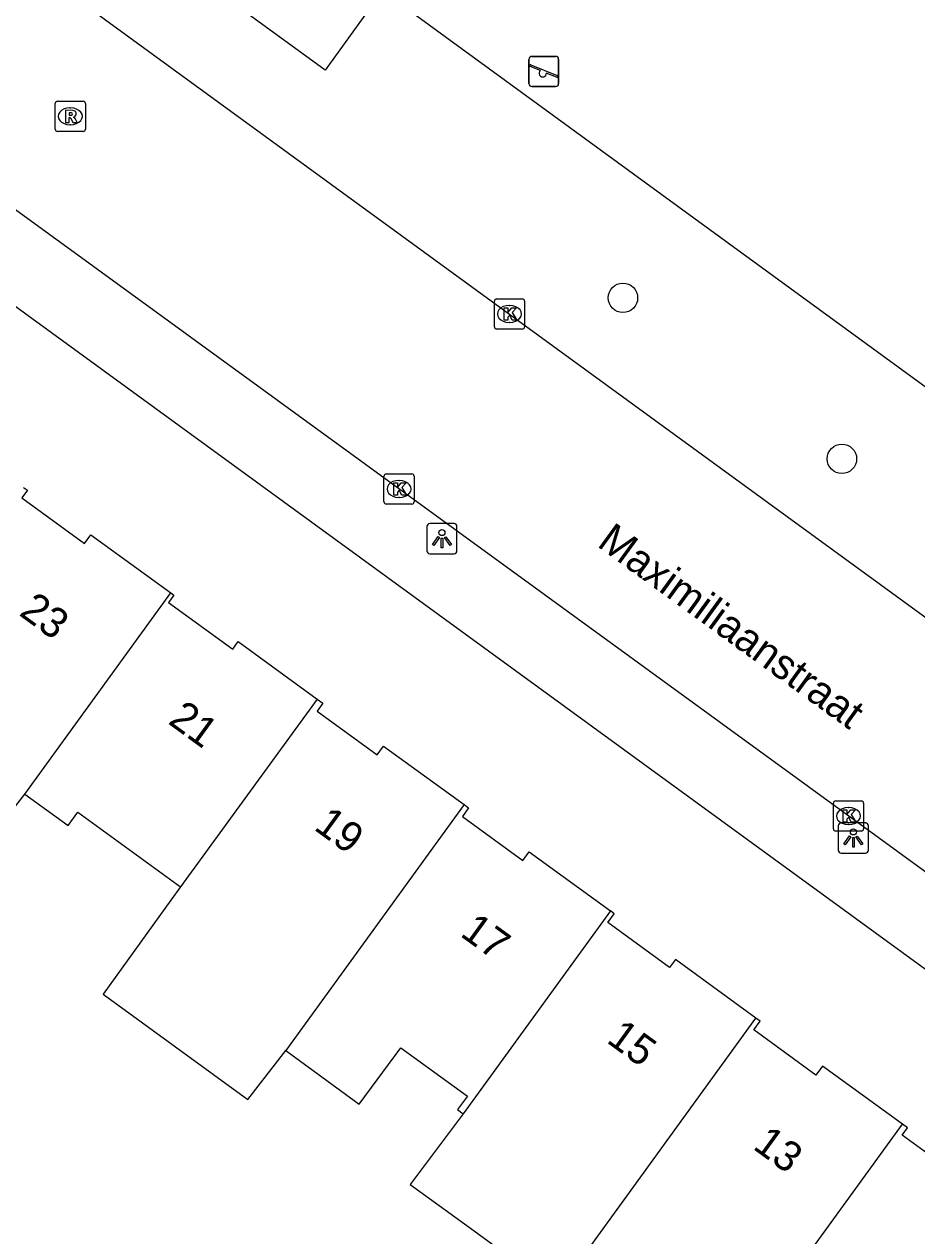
# Model space of a CAD drawing. Extents: x 159675 to 160530, y 382179 to 382901.
# Drawn here: x 160046.7 to 160076.32, y 382398.02 to 382438.2 of the extents above; entities that cross this region are included whole.
import ezdxf

# ---------------------------------------------------------------- set-up
doc = ezdxf.new("R2010")
doc.units = 0
for name, color, linetype in [('IMGEO_Boom', 7, 'Continuous'), ('IMGEO_Kolk', 7, 'Continuous'), ('IMGEO_Lichtpunt', 7, 'Continuous'), ('IMGEO_Openbare_ruimte_label', 7, 'Continuous'), ('IMGEO_Pand', 7, 'Continuous'), ('IMGEO_Pand_nummerreeks', 7, 'Continuous'), ('IMGEO_Rijbaan_lokaal_open', 7, 'Continuous'), ('IMGEO_Rioolput', 7, 'Continuous'), ('IMGEO_Speelvoorziening', 7, 'Continuous'), ('IMGEO_Voetpad_open', 7, 'Continuous')]:
    doc.layers.add(name, color=color, linetype=linetype)

msp = doc.modelspace()

# ---------------------------------------------------------------- linework, layer by layer
at = {"layer": 'IMGEO_Boom'}
for centre in [(160066.569, 382429.126), (160073.836, 382423.786)]:
    msp.add_circle(centre, 0.489, dxfattribs=at)
at = {"layer": 'IMGEO_Kolk'}
for p, q in [((160062.303, 382428.165), (160062.303, 382429.017)), ((160062.378, 382429.091), (160063.23, 382429.091)), ((160063.304, 382429.017), (160063.304, 382428.165)), ((160062.791, 382428.871), (160062.816, 382428.871)), ((160062.814, 382428.311), (160062.789, 382428.311)), ((160063.23, 382428.091), (160062.378, 382428.091)), ((160058.64, 382422.361), (160058.64, 382423.213)), ((160058.715, 382423.287), (160059.567, 382423.287)), ((160059.128, 382423.067), (160059.153, 382423.067)), ((160059.641, 382423.213), (160059.641, 382422.361)), ((160059.151, 382422.507), (160059.126, 382422.507)), ((160059.567, 382422.287), (160058.715, 382422.287)), ((160073.554, 382411.516), (160073.554, 382412.368)), ((160073.629, 382412.442), (160074.481, 382412.442)), ((160074.042, 382412.222), (160074.067, 382412.222)), ((160074.555, 382412.368), (160074.555, 382411.516)), ((160074.065, 382411.662), (160074.04, 382411.662)), ((160074.481, 382411.442), (160073.629, 382411.442))]:
    msp.add_line(p, q, dxfattribs=at)
for points in [[(160062.303, 382428.165), (160062.303, 382429.017)], [(160062.378, 382429.091), (160063.23, 382429.091)], [(160063.304, 382429.017), (160063.304, 382428.165)], [(160062.624, 382428.791), (160062.747, 382428.791), (160062.747, 382428.64), (160062.877, 382428.791), (160063.041, 382428.791), (160062.895, 382428.64), (160063.048, 382428.391), (160062.896, 382428.391), (160062.811, 382428.555), (160062.747, 382428.488), (160062.747, 382428.391), (160062.624, 382428.391), (160062.624, 382428.791)], [(160063.23, 382428.091), (160062.378, 382428.091)], [(160058.64, 382422.361), (160058.64, 382423.213)], [(160058.715, 382423.287), (160059.567, 382423.287)], [(160058.961, 382422.987), (160059.084, 382422.987), (160059.084, 382422.836), (160059.214, 382422.987), (160059.378, 382422.987), (160059.232, 382422.836), (160059.385, 382422.587), (160059.233, 382422.587), (160059.148, 382422.751), (160059.084, 382422.684), (160059.084, 382422.587), (160058.961, 382422.587), (160058.961, 382422.987)], [(160059.641, 382423.213), (160059.641, 382422.361)], [(160059.567, 382422.287), (160058.715, 382422.287)], [(160073.554, 382411.516), (160073.554, 382412.368)], [(160073.629, 382412.442), (160074.481, 382412.442)], [(160073.875, 382412.142), (160073.998, 382412.142), (160073.998, 382411.991), (160074.128, 382412.142), (160074.292, 382412.142), (160074.146, 382411.991), (160074.299, 382411.742), (160074.147, 382411.742), (160074.062, 382411.906), (160073.998, 382411.839), (160073.998, 382411.742), (160073.875, 382411.742), (160073.875, 382412.142)], [(160074.555, 382412.368), (160074.555, 382411.516)], [(160074.481, 382411.442), (160073.629, 382411.442)]]:
    msp.add_lwpolyline(points, dxfattribs=at)
for centre, start, end in [((160062.38, 382429.015), 91.552, 178.448), ((160062.38, 382429.015), 91.552, 178.448), ((160063.228, 382429.015), 1.552, 88.448), ((160063.228, 382429.015), 1.552, 88.448), ((160062.38, 382428.167), 181.552, 268.448), ((160062.38, 382428.167), 181.552, 268.448), ((160063.228, 382428.167), 271.552, 358.448), ((160063.228, 382428.167), 271.552, 358.448), ((160058.717, 382423.211), 91.552, 178.448), ((160058.717, 382423.211), 91.552, 178.448), ((160059.565, 382423.211), 1.552, 88.448), ((160059.565, 382423.211), 1.552, 88.448), ((160058.717, 382422.363), 181.552, 268.448), ((160058.717, 382422.363), 181.552, 268.448), ((160059.565, 382422.363), 271.552, 358.448), ((160059.565, 382422.363), 271.552, 358.448), ((160073.631, 382412.366), 91.552, 178.448), ((160073.631, 382412.366), 91.552, 178.448), ((160074.479, 382412.366), 1.552, 88.448), ((160074.479, 382412.366), 1.552, 88.448), ((160073.631, 382411.518), 181.552, 268.448), ((160073.631, 382411.518), 181.552, 268.448), ((160074.479, 382411.518), 271.552, 358.448), ((160074.479, 382411.518), 271.552, 358.448)]:
    msp.add_arc(centre, 0.0765, start, end, dxfattribs=at)
for centre, major_axis, ratio, start_param, end_param in [((160062.79, 382428.591), (-0.387, 0.002), 0.722429, 4.712389, 7.853982), ((160062.815, 382428.591), (-0.39, 0.002), 0.717154, 1.570796, 4.712389), ((160059.127, 382422.787), (-0.387, 0.002), 0.722429, 4.712389, 7.853982), ((160059.152, 382422.787), (-0.39, 0.002), 0.717154, 1.570796, 4.712389), ((160074.041, 382411.942), (-0.387, 0.002), 0.722429, 4.712389, 7.853982), ((160074.066, 382411.942), (-0.39, 0.002), 0.717154, 1.570796, 4.712389)]:
    msp.add_ellipse(centre, major_axis=major_axis, ratio=ratio, start_param=start_param, end_param=end_param, dxfattribs=at)
at = {"layer": 'IMGEO_Lichtpunt'}
for p, q in [((160060.065, 382421.543), (160060.065, 382420.736)), ((160060.065, 382421.543), (160060.065, 382420.736)), ((160060.967, 382421.638), (160060.159, 382421.638)), ((160060.967, 382421.638), (160060.159, 382421.638)), ((160061.061, 382420.736), (160061.061, 382421.543)), ((160061.061, 382420.736), (160061.061, 382421.543)), ((160060.159, 382420.642), (160060.967, 382420.642)), ((160060.159, 382420.642), (160060.967, 382420.642)), ((160074.619, 382411.71), (160073.811, 382411.71)), ((160074.619, 382411.71), (160073.811, 382411.71)), ((160073.717, 382411.615), (160073.717, 382410.808)), ((160073.717, 382411.615), (160073.717, 382410.808)), ((160074.713, 382410.808), (160074.713, 382411.615)), ((160074.713, 382410.808), (160074.713, 382411.615)), ((160073.811, 382410.714), (160074.619, 382410.714)), ((160073.811, 382410.714), (160074.619, 382410.714))]:
    msp.add_line(p, q, dxfattribs=at)
for points in [[(160060.439, 382421.207), (160060.478, 382421.179), (160060.29, 382420.917), (160060.252, 382420.944), (160060.439, 382421.207)], [(160060.541, 382421.159), (160060.588, 382421.159), (160060.588, 382420.837), (160060.541, 382420.837), (160060.541, 382421.159)], [(160060.651, 382421.179), (160060.689, 382421.206), (160060.876, 382420.944), (160060.837, 382420.916), (160060.651, 382421.179)], [(160074.091, 382411.279), (160074.13, 382411.251), (160073.942, 382410.989), (160073.904, 382411.016), (160074.091, 382411.279)], [(160074.303, 382411.251), (160074.341, 382411.278), (160074.528, 382411.016), (160074.489, 382410.988), (160074.303, 382411.251)], [(160074.193, 382411.231), (160074.24, 382411.231), (160074.24, 382410.909), (160074.193, 382410.909), (160074.193, 382411.231)]]:
    msp.add_lwpolyline(points, dxfattribs=at)
for centre in [(160060.564, 382421.341), (160074.216, 382411.413)]:
    msp.add_circle(centre, 0.0994, dxfattribs=at)
for centre, start, end in [((160060.159, 382421.543), 90, 180), ((160060.159, 382421.543), 90, 180), ((160060.967, 382421.543), 0, 90), ((160060.967, 382421.543), 0, 90), ((160060.159, 382420.736), 180, 270), ((160060.159, 382420.736), 180, 270), ((160060.967, 382420.736), 270, 0), ((160060.967, 382420.736), 270, 360), ((160073.811, 382411.615), 90, 180), ((160073.811, 382411.615), 90, 180), ((160074.619, 382411.615), 0, 90), ((160074.619, 382411.615), 0, 90), ((160073.811, 382410.808), 180, 270), ((160073.811, 382410.808), 180, 270), ((160074.619, 382410.808), 270, 0), ((160074.619, 382410.808), 270, 360)]:
    msp.add_arc(centre, 0.0946, start, end, dxfattribs=at)
at = {"layer": 'IMGEO_Pand'}
for points in [[(160046.682, 382422.833), (160046.805, 382422.744), (160046.62, 382422.49), (160048.7, 382420.976), (160048.913, 382421.27), (160051.563, 382419.341)], [(160046.719, 382412.671), (160051.563, 382419.341)], [(160051.563, 382419.341), (160051.661, 382419.269), (160051.485, 382419.028), (160053.62, 382417.473), (160053.804, 382417.726), (160056.422, 382415.82)], [(160042.201, 382416.661), (160040.904, 382414.902), (160045.725, 382411.376), (160045.904, 382411.621), (160046.719, 382412.671)], [(160056.422, 382415.82), (160051.892, 382409.591)], [(160056.422, 382415.82), (160056.613, 382415.681), (160056.422, 382415.419), (160058.412, 382413.969), (160058.626, 382414.263), (160061.297, 382412.318)], [(160046.719, 382412.671), (160048.156, 382411.625), (160048.483, 382412.073), (160051.892, 382409.591)], [(160061.297, 382412.318), (160055.378, 382404.167)], [(160061.297, 382412.318), (160061.448, 382412.208), (160061.245, 382411.93), (160063.252, 382410.469), (160063.461, 382410.756), (160066.154, 382408.795)], [(160051.892, 382409.591), (160051.57, 382409.148), (160049.32, 382406.038), (160054.119, 382402.544), (160055.378, 382404.167)], [(160066.154, 382408.795), (160061.268, 382402.066)], [(160070.984, 382405.234), (160068.311, 382407.18), (160068.119, 382406.918), (160066.069, 382408.41), (160066.282, 382408.702), (160066.154, 382408.795)], [(160065.185, 382397.247), (160070.984, 382405.234)], [(160075.846, 382401.717), (160073.194, 382403.648), (160072.976, 382403.347), (160070.91, 382404.851), (160071.118, 382405.136), (160070.984, 382405.234)], [(160055.378, 382404.167), (160057.817, 382402.39), (160059.203, 382404.258), (160061.406, 382402.654), (160061.078, 382402.204), (160061.268, 382402.066)], [(160061.268, 382402.066), (160059.51, 382399.725), (160061.629, 382398.181), (160064.228, 382396.288), (160064.398, 382396.164), (160065.185, 382397.247)], [(160070.065, 382393.754), (160075.846, 382401.717)], [(160080.833, 382398.104), (160078.087, 382400.103), (160077.906, 382399.854), (160075.84, 382401.359), (160076.013, 382401.596), (160075.846, 382401.717)]]:
    msp.add_lwpolyline(points, dxfattribs=at)
at = {"layer": 'IMGEO_Rijbaan_lokaal_open'}
for points in [[(160018.366, 382460.946), (160123.455, 382384.426)], [(160099.29, 382393.592), (160034.415, 382440.769)]]:
    msp.add_lwpolyline(points, dxfattribs=at)
at = {"layer": 'IMGEO_Rioolput'}
for p, q in [((160047.729, 382434.721), (160047.729, 382435.573)), ((160047.804, 382435.647), (160048.656, 382435.647)), ((160048.217, 382435.427), (160048.242, 382435.427)), ((160048.73, 382435.573), (160048.73, 382434.721)), ((160048.656, 382434.647), (160047.804, 382434.647)), ((160048.24, 382434.867), (160048.215, 382434.867))]:
    msp.add_line(p, q, dxfattribs=at)
for points in [[(160047.729, 382434.721), (160047.729, 382435.573)], [(160047.804, 382435.647), (160048.656, 382435.647)], [(160048.73, 382435.573), (160048.73, 382434.721)], [(160048.318, 382435.345), (160048.066, 382435.347), (160048.066, 382434.947)], [(160048.066, 382434.947), (160048.19, 382434.947), (160048.19, 382435.109), (160048.201, 382435.109)], [(160048.244, 382435.266), (160048.19, 382435.266), (160048.19, 382435.185)], [(160048.19, 382435.185), (160048.242, 382435.185)], [(160048.248, 382435.08), (160048.319, 382434.947), (160048.459, 382434.947), (160048.394, 382435.073)], [(160048.656, 382434.647), (160047.804, 382434.647)]]:
    msp.add_lwpolyline(points, dxfattribs=at)
for centre, radius, start, end in [((160047.806, 382435.571), 0.0765, 91.552, 178.448), ((160047.806, 382435.571), 0.0765, 91.552, 178.448), ((160048.654, 382435.571), 0.0765, 1.552, 88.448), ((160048.654, 382435.571), 0.0765, 1.552, 88.448), ((160048.2, 382435.056), 0.0533, 26.0293, 88.6989), ((160048.226, 382435.374), 0.19, 274.7715, 282.9687), ((160048.25, 382435.17), 0.0964, 77.0061, 93.1865), ((160048.264, 382435.227), 0.0378, 276.6634, 79.6772), ((160048.317, 382435.235), 0.109, 350.3612, 89.416), ((160048.315, 382435.235), 0.112, 277.5842, 350.9817), ((160048.299, 382435.02), 0.108, 29.5134, 73.7905), ((160047.806, 382434.723), 0.0765, 181.552, 268.448), ((160047.806, 382434.723), 0.0765, 181.552, 268.448), ((160048.654, 382434.723), 0.0765, 271.552, 358.448), ((160048.654, 382434.723), 0.0765, 271.552, 358.448)]:
    msp.add_arc(centre, radius, start, end, dxfattribs=at)
for centre, major_axis, ratio, start_param, end_param in [((160048.216, 382435.147), (-0.387, 0.002), 0.722429, 4.712389, 7.853982), ((160048.241, 382435.147), (-0.39, 0.002), 0.717154, 1.570796, 4.712389)]:
    msp.add_ellipse(centre, major_axis=major_axis, ratio=ratio, start_param=start_param, end_param=end_param, dxfattribs=at)
at = {"layer": 'IMGEO_Speelvoorziening'}
for p, q in [((160063.446, 382436.234), (160063.446, 382437.034)), ((160063.446, 382437.034), (160063.446, 382436.234)), ((160063.546, 382437.134), (160064.336, 382437.134)), ((160064.336, 382437.134), (160063.546, 382437.134)), ((160064.436, 382437.034), (160064.436, 382436.234)), ((160064.436, 382436.234), (160064.436, 382437.034)), ((160063.829, 382436.662), (160063.49, 382436.799)), ((160063.515, 382436.859), (160064.391, 382436.506)), ((160064.367, 382436.446), (160064.027, 382436.583)), ((160064.336, 382436.134), (160063.546, 382436.134)), ((160063.546, 382436.134), (160064.336, 382436.134))]:
    msp.add_line(p, q, dxfattribs=at)
for centre, radius, start, end in [((160063.546, 382437.034), 0.1, 90, 180), ((160063.546, 382437.034), 0.1, 90, 180), ((160064.336, 382437.034), 0.1, 0, 90), ((160064.336, 382437.034), 0.1, 360, 90), ((160063.503, 382436.829), 0.0327, 68.078, 248.078), ((160063.908, 382436.572), 0.12, 130.9928, 5.1632), ((160063.546, 382436.234), 0.1, 180, 270), ((160063.546, 382436.234), 0.1, 180, 270), ((160064.336, 382436.234), 0.1, 270, 0), ((160064.336, 382436.234), 0.1, 270, 0), ((160064.379, 382436.476), 0.0327, 248.078, 68.078)]:
    msp.add_arc(centre, radius, start, end, dxfattribs=at)
at = {"layer": 'IMGEO_Voetpad_open'}
for points in [[(160058.575, 382439.306), (160056.683, 382436.674), (160051.245, 382440.646), (160052.977, 382443.048), (160054.806, 382445.584), (160060.282, 382441.681), (160058.575, 382439.306)], [(160125.462, 382390.566), (160059.604, 382438.555), (160062.271, 382442.237)], [(160083.531, 382401.81), (160034.768, 382437.312), (160034.251, 382436.61)]]:
    msp.add_lwpolyline(points, dxfattribs=at)

# ---------------------------------------------------------------- texts
at = {"layer": 'IMGEO_Openbare_ruimte_label'}
msp.add_text('Maximiliaanstraat', height=1, rotation=323.9895, dxfattribs=at).set_placement((160065.676, 382420.908))
at = {"layer": 'IMGEO_Pand_nummerreeks'}
for s, rotation, p in [('23', 323.9896, (160046.494, 382418.624)), ('21', 323.9896, (160051.44, 382415.029)), ('19', 323.9896, (160056.278, 382411.513)), ('17', 323.9907, (160061.133, 382407.984)), ('15', 323.9896, (160065.989, 382404.456)), ('13', 323.9896, (160070.844, 382400.927))]:
    msp.add_text(s, height=1, rotation=rotation, dxfattribs=at).set_placement(p)

doc.saveas('drawing.dxf')
